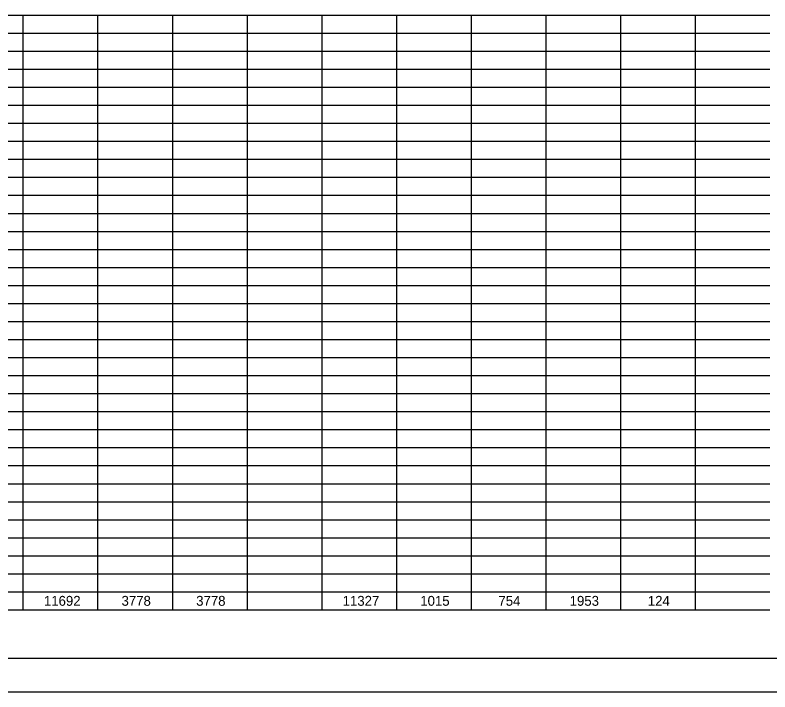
# Model space of a CAD drawing. Extents: x 0 to 34, y 0 to 22.
# Drawn here: x 11.72 to 23.04, y 0 to 10.15 of the extents above; entities that cross this region are included whole.
import ezdxf

# ---------------------------------------------------------------- set-up
doc = ezdxf.new("R2010")
doc.units = 0
for name, color, linetype in [('SH_Border', 7, 'Continuous'), ('SH_Cut_Line', 7, 'Continuous'), ('SH_Text', 7, 'Continuous')]:
    doc.layers.add(name, color=color, linetype=linetype)

msp = doc.modelspace()

# ---------------------------------------------------------------- linework, layer by layer
at = {"layer": 'SH_Border'}
msp.add_lwpolyline([(1.5, 21.5), (33.5, 21.5), (33.5, 0.5), (1.5, 0.5)], close=True, dxfattribs=at)
at = {"layer": 'SH_Cut_Line'}
msp.add_lwpolyline([(0, 0), (34, 0), (34, 22), (0, 22)], close=True, dxfattribs=at)
at = {"layer": 'SH_Text'}
for p, q in [((10.722, 10.152), (11.841, 10.152)), ((11.841, 10.152), (12.961, 10.152)), ((11.841, 10.152), (11.841, 9.881)), ((12.961, 10.152), (14.081, 10.152)), ((12.961, 10.152), (12.961, 9.881)), ((14.081, 10.152), (16.321, 10.152)), ((14.081, 10.152), (14.081, 9.881)), ((15.201, 10.152), (15.201, 9.881)), ((16.321, 10.152), (23.041, 10.152)), ((16.321, 10.152), (16.321, 9.881)), ((17.441, 10.152), (17.441, 9.881)), ((18.561, 10.152), (18.561, 9.881)), ((19.681, 10.152), (19.681, 9.881)), ((20.801, 10.152), (20.801, 9.881)), ((21.921, 10.152), (21.921, 9.881)), ((10.722, 9.881), (11.841, 9.881)), ((11.841, 9.881), (12.961, 9.881)), ((11.841, 9.881), (11.841, 9.611)), ((12.961, 9.881), (14.081, 9.881)), ((12.961, 9.881), (12.961, 9.611)), ((14.081, 9.881), (16.321, 9.881)), ((14.081, 9.881), (14.081, 9.611)), ((15.201, 9.881), (15.201, 9.611)), ((16.321, 9.881), (23.041, 9.881)), ((16.321, 9.881), (16.321, 9.611)), ((17.441, 9.881), (17.441, 9.611)), ((18.561, 9.881), (18.561, 9.611)), ((19.681, 9.881), (19.681, 9.611)), ((20.801, 9.881), (20.801, 9.611)), ((21.921, 9.881), (21.921, 9.611)), ((10.722, 9.611), (11.841, 9.611)), ((11.841, 9.611), (12.961, 9.611)), ((11.841, 9.611), (11.841, 9.341)), ((12.961, 9.611), (14.081, 9.611)), ((12.961, 9.611), (12.961, 9.341)), ((14.081, 9.611), (16.321, 9.611)), ((14.081, 9.611), (14.081, 9.341)), ((15.201, 9.611), (15.201, 9.341)), ((16.321, 9.611), (23.041, 9.611)), ((16.321, 9.611), (16.321, 9.341)), ((17.441, 9.611), (17.441, 9.341)), ((18.561, 9.611), (18.561, 9.341)), ((19.681, 9.611), (19.681, 9.341)), ((20.801, 9.611), (20.801, 9.341)), ((21.921, 9.611), (21.921, 9.341)), ((10.722, 9.341), (11.841, 9.341)), ((11.841, 9.341), (12.961, 9.341)), ((11.841, 9.341), (11.841, 9.07)), ((12.961, 9.341), (14.081, 9.341)), ((12.961, 9.341), (12.961, 9.07)), ((14.081, 9.341), (16.321, 9.341)), ((14.081, 9.341), (14.081, 9.07)), ((15.201, 9.341), (15.201, 9.07)), ((16.321, 9.341), (23.041, 9.341)), ((16.321, 9.341), (16.321, 9.07)), ((17.441, 9.341), (17.441, 9.07)), ((18.561, 9.341), (18.561, 9.07)), ((19.681, 9.341), (19.681, 9.07)), ((20.801, 9.341), (20.801, 9.07)), ((21.921, 9.341), (21.921, 9.07)), ((10.722, 9.07), (11.841, 9.07)), ((11.841, 9.07), (12.961, 9.07)), ((11.841, 9.07), (11.841, 8.8)), ((12.961, 9.07), (14.081, 9.07)), ((12.961, 9.07), (12.961, 8.8)), ((14.081, 9.07), (16.321, 9.07)), ((14.081, 9.07), (14.081, 8.8)), ((15.201, 9.07), (15.201, 8.8)), ((16.321, 9.07), (23.041, 9.07)), ((16.321, 9.07), (16.321, 8.8)), ((17.441, 9.07), (17.441, 8.8)), ((18.561, 9.07), (18.561, 8.8)), ((19.681, 9.07), (19.681, 8.8)), ((20.801, 9.07), (20.801, 8.8)), ((21.921, 9.07), (21.921, 8.8)), ((10.722, 8.8), (11.841, 8.8)), ((11.841, 8.8), (12.961, 8.8)), ((11.841, 8.8), (11.841, 8.53)), ((12.961, 8.8), (14.081, 8.8)), ((12.961, 8.8), (12.961, 8.53)), ((14.081, 8.8), (16.321, 8.8)), ((14.081, 8.8), (14.081, 8.53)), ((15.201, 8.8), (15.201, 8.53)), ((16.321, 8.8), (23.041, 8.8)), ((16.321, 8.8), (16.321, 8.53)), ((17.441, 8.8), (17.441, 8.53)), ((18.561, 8.8), (18.561, 8.53)), ((19.681, 8.8), (19.681, 8.53)), ((20.801, 8.8), (20.801, 8.53)), ((21.921, 8.8), (21.921, 8.53)), ((10.722, 8.53), (11.841, 8.53)), ((11.841, 8.53), (12.961, 8.53)), ((11.841, 8.53), (11.841, 8.259)), ((12.961, 8.53), (14.081, 8.53)), ((12.961, 8.53), (12.961, 8.259)), ((14.081, 8.53), (16.321, 8.53)), ((14.081, 8.53), (14.081, 8.259)), ((15.201, 8.53), (15.201, 8.259)), ((16.321, 8.53), (23.041, 8.53)), ((16.321, 8.53), (16.321, 8.259)), ((17.441, 8.53), (17.441, 8.259)), ((18.561, 8.53), (18.561, 8.259)), ((19.681, 8.53), (19.681, 8.259)), ((20.801, 8.53), (20.801, 8.259)), ((21.921, 8.53), (21.921, 8.259)), ((10.722, 8.259), (11.841, 8.259)), ((11.841, 8.259), (12.961, 8.259)), ((11.841, 8.259), (11.841, 7.989)), ((12.961, 8.259), (14.081, 8.259)), ((12.961, 8.259), (12.961, 7.989)), ((14.081, 8.259), (16.321, 8.259)), ((14.081, 8.259), (14.081, 7.989)), ((15.201, 8.259), (15.201, 7.989)), ((16.321, 8.259), (23.041, 8.259)), ((16.321, 8.259), (16.321, 7.989)), ((17.441, 8.259), (17.441, 7.989)), ((18.561, 8.259), (18.561, 7.989)), ((19.681, 8.259), (19.681, 7.989)), ((20.801, 8.259), (20.801, 7.989)), ((21.921, 8.259), (21.921, 7.989)), ((10.722, 7.989), (11.841, 7.989)), ((11.841, 7.989), (12.961, 7.989)), ((11.841, 7.989), (11.841, 7.719)), ((12.961, 7.989), (14.081, 7.989)), ((12.961, 7.989), (12.961, 7.719)), ((14.081, 7.989), (16.321, 7.989)), ((14.081, 7.989), (14.081, 7.719)), ((15.201, 7.989), (15.201, 7.719)), ((16.321, 7.989), (23.041, 7.989)), ((16.321, 7.989), (16.321, 7.719)), ((17.441, 7.989), (17.441, 7.719)), ((18.561, 7.989), (18.561, 7.719)), ((19.681, 7.989), (19.681, 7.719)), ((20.801, 7.989), (20.801, 7.719)), ((21.921, 7.989), (21.921, 7.719)), ((10.722, 7.719), (11.841, 7.719)), ((11.841, 7.719), (12.961, 7.719)), ((11.841, 7.719), (11.841, 7.449)), ((12.961, 7.719), (14.081, 7.719)), ((12.961, 7.719), (12.961, 7.449)), ((14.081, 7.719), (16.321, 7.719)), ((14.081, 7.719), (14.081, 7.449)), ((15.201, 7.719), (15.201, 7.449)), ((16.321, 7.719), (23.041, 7.719)), ((16.321, 7.719), (16.321, 7.449)), ((17.441, 7.719), (17.441, 7.449)), ((18.561, 7.719), (18.561, 7.449)), ((19.681, 7.719), (19.681, 7.449)), ((20.801, 7.719), (20.801, 7.449)), ((21.921, 7.719), (21.921, 7.449)), ((10.722, 7.449), (11.841, 7.449)), ((11.841, 7.449), (12.961, 7.449)), ((11.841, 7.449), (11.841, 7.178)), ((12.961, 7.449), (14.081, 7.449)), ((12.961, 7.449), (12.961, 7.178)), ((14.081, 7.449), (16.321, 7.449)), ((14.081, 7.449), (14.081, 7.178)), ((15.201, 7.449), (15.201, 7.178)), ((16.321, 7.449), (23.041, 7.449)), ((16.321, 7.449), (16.321, 7.178)), ((17.441, 7.449), (17.441, 7.178)), ((18.561, 7.449), (18.561, 7.178)), ((19.681, 7.449), (19.681, 7.178)), ((20.801, 7.449), (20.801, 7.178)), ((21.921, 7.449), (21.921, 7.178)), ((10.722, 7.178), (11.841, 7.178)), ((11.841, 7.178), (12.961, 7.178)), ((11.841, 7.178), (11.841, 6.908)), ((12.961, 7.178), (14.081, 7.178)), ((12.961, 7.178), (12.961, 6.908)), ((14.081, 7.178), (16.321, 7.178)), ((14.081, 7.178), (14.081, 6.908)), ((15.201, 7.178), (15.201, 6.908)), ((16.321, 7.178), (23.041, 7.178)), ((16.321, 7.178), (16.321, 6.908)), ((17.441, 7.178), (17.441, 6.908)), ((18.561, 7.178), (18.561, 6.908)), ((19.681, 7.178), (19.681, 6.908)), ((20.801, 7.178), (20.801, 6.908)), ((21.921, 7.178), (21.921, 6.908)), ((10.722, 6.908), (11.841, 6.908)), ((11.841, 6.908), (12.961, 6.908)), ((11.841, 6.908), (11.841, 6.638)), ((12.961, 6.908), (14.081, 6.908)), ((12.961, 6.908), (12.961, 6.638)), ((14.081, 6.908), (16.321, 6.908)), ((14.081, 6.908), (14.081, 6.638)), ((15.201, 6.908), (15.201, 6.638)), ((16.321, 6.908), (23.041, 6.908)), ((16.321, 6.908), (16.321, 6.638)), ((17.441, 6.908), (17.441, 6.638)), ((18.561, 6.908), (18.561, 6.638)), ((19.681, 6.908), (19.681, 6.638)), ((20.801, 6.908), (20.801, 6.638)), ((21.921, 6.908), (21.921, 6.638)), ((10.722, 6.638), (11.841, 6.638)), ((11.841, 6.638), (12.961, 6.638)), ((11.841, 6.638), (11.841, 6.367)), ((12.961, 6.638), (14.081, 6.638)), ((12.961, 6.638), (12.961, 6.367)), ((14.081, 6.638), (16.321, 6.638)), ((14.081, 6.638), (14.081, 6.367)), ((15.201, 6.638), (15.201, 6.367)), ((16.321, 6.638), (23.041, 6.638)), ((16.321, 6.638), (16.321, 6.367)), ((17.441, 6.638), (17.441, 6.367)), ((18.561, 6.638), (18.561, 6.367)), ((19.681, 6.638), (19.681, 6.367)), ((20.801, 6.638), (20.801, 6.367)), ((21.921, 6.638), (21.921, 6.367)), ((10.722, 6.367), (11.841, 6.367)), ((11.841, 6.367), (12.961, 6.367)), ((11.841, 6.367), (11.841, 6.097)), ((12.961, 6.367), (14.081, 6.367)), ((12.961, 6.367), (12.961, 6.097)), ((14.081, 6.367), (16.321, 6.367)), ((14.081, 6.367), (14.081, 6.097)), ((15.201, 6.367), (15.201, 6.097)), ((16.321, 6.367), (23.041, 6.367)), ((16.321, 6.367), (16.321, 6.097)), ((17.441, 6.367), (17.441, 6.097)), ((18.561, 6.367), (18.561, 6.097)), ((19.681, 6.367), (19.681, 6.097)), ((20.801, 6.367), (20.801, 6.097)), ((21.921, 6.367), (21.921, 6.097)), ((10.722, 6.097), (11.841, 6.097)), ((11.841, 6.097), (12.961, 6.097)), ((11.841, 6.097), (11.841, 5.556)), ((12.961, 6.097), (14.081, 6.097)), ((12.961, 6.097), (12.961, 5.556)), ((14.081, 6.097), (16.321, 6.097)), ((14.081, 6.097), (14.081, 5.556)), ((15.201, 6.097), (15.201, 5.556)), ((16.321, 6.097), (23.041, 6.097)), ((16.321, 6.097), (16.321, 5.556)), ((17.441, 6.097), (17.441, 5.556)), ((18.561, 6.097), (18.561, 5.556)), ((19.681, 6.097), (19.681, 5.556)), ((20.801, 6.097), (20.801, 5.556)), ((21.921, 6.097), (21.921, 5.556)), ((10.722, 5.827), (11.841, 5.827)), ((11.841, 5.827), (12.961, 5.827)), ((12.961, 5.827), (14.081, 5.827)), ((14.081, 5.827), (16.321, 5.827)), ((16.321, 5.827), (23.041, 5.827)), ((10.722, 5.556), (11.841, 5.556)), ((11.841, 5.556), (12.961, 5.556)), ((11.841, 5.556), (11.841, 5.286)), ((12.961, 5.556), (14.081, 5.556)), ((12.961, 5.556), (12.961, 5.286)), ((14.081, 5.556), (16.321, 5.556)), ((14.081, 5.556), (14.081, 5.286)), ((15.201, 5.556), (15.201, 5.286)), ((16.321, 5.556), (23.041, 5.556)), ((16.321, 5.556), (16.321, 5.286)), ((17.441, 5.556), (17.441, 5.286)), ((18.561, 5.556), (18.561, 5.286)), ((19.681, 5.556), (19.681, 5.286)), ((20.801, 5.556), (20.801, 5.286)), ((21.921, 5.556), (21.921, 5.286)), ((10.722, 5.286), (11.841, 5.286)), ((11.841, 5.286), (12.961, 5.286)), ((11.841, 5.286), (11.841, 5.016)), ((12.961, 5.286), (14.081, 5.286)), ((12.961, 5.286), (12.961, 5.016)), ((14.081, 5.286), (16.321, 5.286)), ((14.081, 5.286), (14.081, 5.016)), ((15.201, 5.286), (15.201, 5.016)), ((16.321, 5.286), (23.041, 5.286)), ((16.321, 5.286), (16.321, 5.016)), ((17.441, 5.286), (17.441, 5.016)), ((18.561, 5.286), (18.561, 5.016)), ((19.681, 5.286), (19.681, 5.016)), ((20.801, 5.286), (20.801, 5.016)), ((21.921, 5.286), (21.921, 5.016)), ((10.722, 5.016), (11.841, 5.016)), ((11.841, 5.016), (12.961, 5.016)), ((11.841, 5.016), (11.841, 4.745)), ((12.961, 5.016), (14.081, 5.016)), ((12.961, 5.016), (12.961, 4.745)), ((14.081, 5.016), (16.321, 5.016)), ((14.081, 5.016), (14.081, 4.745)), ((15.201, 5.016), (15.201, 4.745)), ((16.321, 5.016), (23.041, 5.016)), ((16.321, 5.016), (16.321, 4.745)), ((17.441, 5.016), (17.441, 4.745)), ((18.561, 5.016), (18.561, 4.745)), ((19.681, 5.016), (19.681, 4.745)), ((20.801, 5.016), (20.801, 4.745)), ((21.921, 5.016), (21.921, 4.745)), ((10.722, 4.745), (11.841, 4.745)), ((11.841, 4.745), (12.961, 4.745)), ((11.841, 4.745), (11.841, 4.205)), ((12.961, 4.745), (14.081, 4.745)), ((12.961, 4.745), (12.961, 4.205)), ((14.081, 4.745), (16.321, 4.745)), ((14.081, 4.745), (14.081, 4.205)), ((15.201, 4.745), (15.201, 4.205)), ((16.321, 4.745), (23.041, 4.745)), ((16.321, 4.745), (16.321, 4.205)), ((17.441, 4.745), (17.441, 4.205)), ((18.561, 4.745), (18.561, 4.205)), ((19.681, 4.745), (19.681, 4.205)), ((20.801, 4.745), (20.801, 4.205)), ((21.921, 4.745), (21.921, 4.205)), ((10.722, 4.475), (11.841, 4.475)), ((11.841, 4.475), (12.961, 4.475)), ((12.961, 4.475), (14.081, 4.475)), ((14.081, 4.475), (16.321, 4.475)), ((16.321, 4.475), (23.041, 4.475)), ((10.722, 4.205), (11.841, 4.205)), ((11.841, 4.205), (12.961, 4.205)), ((11.841, 4.205), (11.841, 3.934)), ((12.961, 4.205), (14.081, 4.205)), ((12.961, 4.205), (12.961, 3.934)), ((14.081, 4.205), (16.321, 4.205)), ((14.081, 4.205), (14.081, 3.934)), ((15.201, 4.205), (15.201, 3.934)), ((16.321, 4.205), (23.041, 4.205)), ((16.321, 4.205), (16.321, 3.934)), ((17.441, 4.205), (17.441, 3.934)), ((18.561, 4.205), (18.561, 3.934)), ((19.681, 4.205), (19.681, 3.934)), ((20.801, 4.205), (20.801, 3.934)), ((21.921, 4.205), (21.921, 3.934)), ((10.722, 3.934), (11.841, 3.934)), ((11.841, 3.934), (12.961, 3.934)), ((11.841, 3.934), (11.841, 3.664)), ((12.961, 3.934), (14.081, 3.934)), ((12.961, 3.934), (12.961, 3.664)), ((14.081, 3.934), (16.321, 3.934)), ((14.081, 3.934), (14.081, 3.664)), ((15.201, 3.934), (15.201, 3.664)), ((16.321, 3.934), (23.041, 3.934)), ((16.321, 3.934), (16.321, 3.664)), ((17.441, 3.934), (17.441, 3.664)), ((18.561, 3.934), (18.561, 3.664)), ((19.681, 3.934), (19.681, 3.664)), ((20.801, 3.934), (20.801, 3.664)), ((21.921, 3.934), (21.921, 3.664)), ((10.722, 3.664), (11.841, 3.664)), ((11.841, 3.664), (12.961, 3.664)), ((11.841, 3.664), (11.841, 3.394)), ((12.961, 3.664), (14.081, 3.664)), ((12.961, 3.664), (12.961, 3.394)), ((14.081, 3.664), (16.321, 3.664)), ((14.081, 3.664), (14.081, 3.394)), ((15.201, 3.664), (15.201, 3.394)), ((16.321, 3.664), (23.041, 3.664)), ((16.321, 3.664), (16.321, 3.394)), ((17.441, 3.664), (17.441, 3.394)), ((18.561, 3.664), (18.561, 3.394)), ((19.681, 3.664), (19.681, 3.394)), ((20.801, 3.664), (20.801, 3.394)), ((21.921, 3.664), (21.921, 3.394)), ((10.722, 3.394), (11.841, 3.394)), ((11.841, 3.394), (12.961, 3.394)), ((11.841, 3.394), (11.841, 2.853)), ((12.961, 3.394), (14.081, 3.394)), ((12.961, 3.394), (12.961, 2.853)), ((14.081, 3.394), (16.321, 3.394)), ((14.081, 3.394), (14.081, 2.853)), ((15.201, 3.394), (15.201, 2.853)), ((16.321, 3.394), (23.041, 3.394)), ((16.321, 3.394), (16.321, 2.853)), ((17.441, 3.394), (17.441, 2.853)), ((18.561, 3.394), (18.561, 2.853)), ((19.681, 3.394), (19.681, 2.853)), ((20.801, 3.394), (20.801, 2.853)), ((21.921, 3.394), (21.921, 2.853)), ((10.722, 3.123), (11.841, 3.123)), ((11.841, 3.123), (12.961, 3.123)), ((12.961, 3.123), (14.081, 3.123)), ((14.081, 3.123), (16.321, 3.123)), ((16.321, 3.123), (23.041, 3.123)), ((10.722, 2.853), (11.841, 2.853)), ((11.841, 2.853), (12.961, 2.853)), ((11.841, 2.853), (11.841, 2.583)), ((12.961, 2.853), (14.081, 2.853)), ((12.961, 2.853), (12.961, 2.583)), ((14.081, 2.853), (16.321, 2.853)), ((14.081, 2.853), (14.081, 2.583)), ((15.201, 2.853), (15.201, 2.583)), ((16.321, 2.853), (23.041, 2.853)), ((16.321, 2.853), (16.321, 2.583)), ((17.441, 2.853), (17.441, 2.583)), ((18.561, 2.853), (18.561, 2.583)), ((19.681, 2.853), (19.681, 2.583)), ((20.801, 2.853), (20.801, 2.583)), ((21.921, 2.853), (21.921, 2.583)), ((10.722, 2.583), (11.841, 2.583)), ((11.841, 2.583), (12.961, 2.583)), ((11.841, 2.583), (11.841, 2.312)), ((12.961, 2.583), (14.081, 2.583)), ((12.961, 2.583), (12.961, 2.312)), ((14.081, 2.583), (16.321, 2.583)), ((14.081, 2.583), (14.081, 2.312)), ((15.201, 2.583), (15.201, 2.312)), ((16.321, 2.583), (23.041, 2.583)), ((16.321, 2.583), (16.321, 2.312)), ((17.441, 2.583), (17.441, 2.312)), ((18.561, 2.583), (18.561, 2.312)), ((19.681, 2.583), (19.681, 2.312)), ((20.801, 2.583), (20.801, 2.312)), ((21.921, 2.583), (21.921, 2.312)), ((10.722, 2.312), (11.841, 2.312)), ((11.841, 2.312), (12.961, 2.312)), ((11.841, 2.312), (11.841, 2.042)), ((12.961, 2.312), (14.081, 2.312)), ((12.961, 2.312), (12.961, 2.042)), ((14.081, 2.312), (16.321, 2.312)), ((14.081, 2.312), (14.081, 2.042)), ((15.201, 2.312), (15.201, 2.042)), ((16.321, 2.312), (23.041, 2.312)), ((16.321, 2.312), (16.321, 2.042)), ((17.441, 2.312), (17.441, 2.042)), ((18.561, 2.312), (18.561, 2.042)), ((19.681, 2.312), (19.681, 2.042)), ((20.801, 2.312), (20.801, 2.042)), ((21.921, 2.312), (21.921, 2.042)), ((10.722, 2.042), (11.841, 2.042)), ((11.841, 2.042), (12.961, 2.042)), ((11.841, 2.042), (11.841, 1.501)), ((12.961, 2.042), (14.081, 2.042)), ((12.961, 2.042), (12.961, 1.501)), ((14.081, 2.042), (16.321, 2.042)), ((14.081, 2.042), (14.081, 1.501)), ((15.201, 2.042), (15.201, 1.501)), ((16.321, 2.042), (23.041, 2.042)), ((16.321, 2.042), (16.321, 1.501)), ((17.441, 2.042), (17.441, 1.501)), ((18.561, 2.042), (18.561, 1.501)), ((19.681, 2.042), (19.681, 1.501)), ((20.801, 2.042), (20.801, 1.501)), ((21.921, 2.042), (21.921, 1.501)), ((10.722, 1.772), (11.841, 1.772)), ((11.841, 1.772), (12.961, 1.772)), ((12.961, 1.772), (14.081, 1.772)), ((14.081, 1.772), (16.321, 1.772)), ((16.321, 1.772), (23.041, 1.772)), ((10.722, 1.501), (11.841, 1.501)), ((11.841, 1.501), (12.961, 1.501)), ((11.841, 1.501), (11.841, 1.231)), ((12.961, 1.501), (14.081, 1.501)), ((12.961, 1.501), (12.961, 1.231)), ((14.081, 1.501), (16.321, 1.501)), ((14.081, 1.501), (14.081, 1.231)), ((15.201, 1.501), (15.201, 1.231)), ((16.321, 1.501), (23.041, 1.501)), ((16.321, 1.501), (16.321, 1.231)), ((17.441, 1.501), (17.441, 1.231)), ((18.561, 1.501), (18.561, 1.231)), ((19.681, 1.501), (19.681, 1.231)), ((20.801, 1.501), (20.801, 1.231)), ((21.921, 1.501), (21.921, 1.231)), ((10.722, 1.231), (11.841, 1.231)), ((11.841, 1.231), (12.961, 1.231)), ((12.961, 1.231), (14.081, 1.231)), ((14.081, 1.231), (16.321, 1.231)), ((16.321, 1.231), (23.041, 1.231))]:
    msp.add_line(p, q, dxfattribs=at)

# ---------------------------------------------------------------- texts
for s, p in [('11692', (12.155, 1.292)), ('3778', (13.319, 1.292)), ('3778', (14.438, 1.292)), ('11327', (16.634, 1.292)), ('1015', (17.798, 1.292)), ('754', (18.97, 1.292)), ('1953', (20.038, 1.292)), ('124', (21.21, 1.292))]:
    msp.add_text(s, height=0.148, dxfattribs=at).set_placement(p)

doc.saveas('drawing.dxf')
